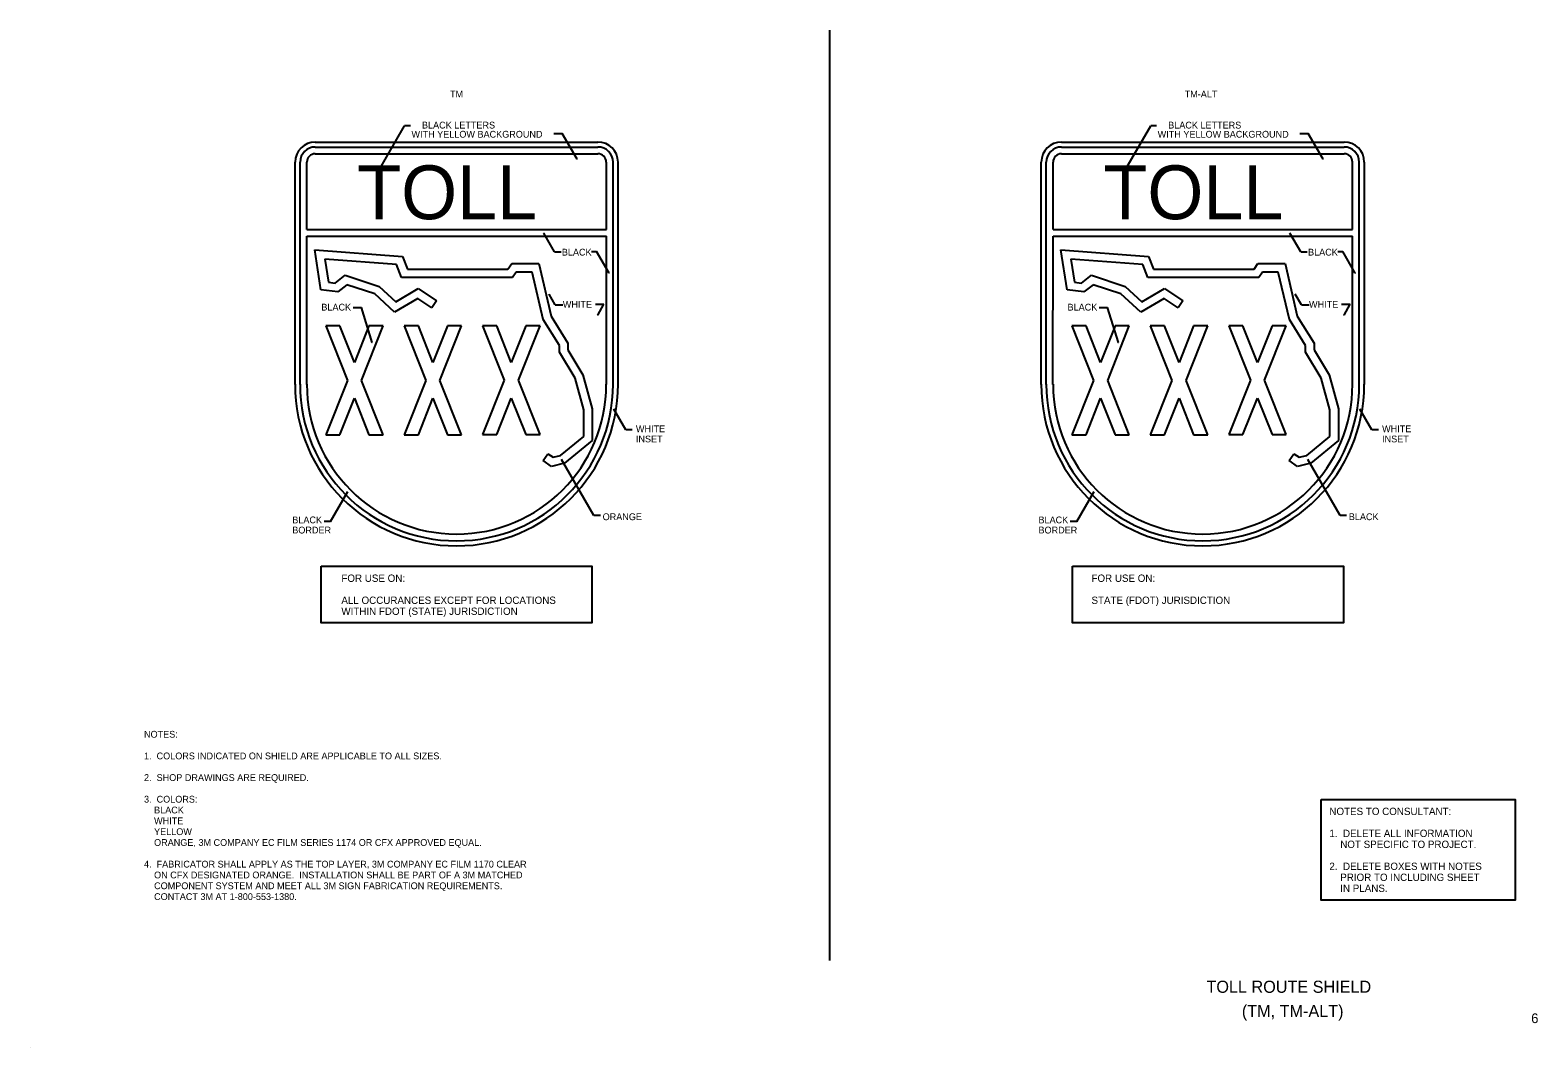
# Model space of a CAD drawing. Extents: x 52204 to 54071, y 10312 to 11572.
import ezdxf

# ---------------------------------------------------------------- set-up
doc = ezdxf.new("R2010")
doc.units = 0
for name, color, linetype in [('AdhocPoint_dp', 7, 'Continuous'), ('Default', 7, 'Continuous'), ('GSDims', 7, 'Continuous'), ('NonPlottingEle_dp', 7, 'Continuous'), ('SignPanel', 7, 'Continuous'), ('TextAlert', 7, 'Continuous'), ('TextMisc', 7, 'Continuous'), ('TextNotes', 7, 'Continuous'), ('TextShtNo', 7, 'Continuous')]:
    doc.layers.add(name, color=color, linetype=linetype)

msp = doc.modelspace()

# ---------------------------------------------------------------- linework, layer by layer
at = {"layer": 'AdhocPoint_dp'}
msp.add_line((52204.2, 10312.4), (52204.2, 10312.4), dxfattribs=at)
at = {"layer": 'GSDims'}
for p, q in [((52634.2, 11395.8), (52667.9, 11454)), ((52675.1, 11454), (52667.9, 11454)), ((52852.7, 11444.4), (52863.1, 11444.4)), ((52881.4, 11412.8), (52863.1, 11444.4)), ((53558.2, 11395.8), (53591.9, 11454)), ((53599.1, 11454), (53591.9, 11454)), ((53776.5, 11444.4), (53786.9, 11444.4)), ((53805.2, 11412.8), (53786.9, 11444.4)), ((52853.5, 11297.9), (52840.1, 11321.1)), ((53777.5, 11297.9), (53764.1, 11321.1)), ((52853.5, 11297.9), (52861.6, 11297.9)), ((52899.3, 11298.3), (52905.5, 11298.3)), ((52921, 11271.5), (52905.5, 11298.3)), ((53777.5, 11297.9), (53785.6, 11297.9)), ((53823.3, 11298.3), (53829.5, 11298.3)), ((53845, 11271.5), (53829.5, 11298.3)), ((52854.4, 11232.5), (52846.8, 11245.6)), ((53778.4, 11232.5), (53770.8, 11245.6)), ((52604, 11228.9), (52614.4, 11228.9)), ((52627.8, 11185.7), (52614.4, 11228.9)), ((52854.4, 11232.5), (52864, 11232.5)), ((52904.2, 11233.3), (52914.7, 11233.3)), ((52907.3, 11219.6), (52914.7, 11233.3)), ((53528, 11228.9), (53538.4, 11228.9)), ((53551.8, 11185.7), (53538.4, 11228.9)), ((53778.4, 11232.5), (53788, 11232.5)), ((53828.2, 11233.3), (53838.7, 11233.3)), ((53831.3, 11219.6), (53838.7, 11233.3)), ((52941.7, 11077.4), (52926.8, 11103.3)), ((53865.7, 11077.4), (53850.8, 11103.3)), ((52949.8, 11077.4), (52941.7, 11077.4)), ((53873.8, 11077.4), (53865.7, 11077.4)), ((52902.4, 10971.4), (52862.3, 11040.9)), ((53826.4, 10971.4), (53786.3, 11040.9)), ((52576.2, 10963.9), (52597.7, 11001.1)), ((53500.2, 10963.9), (53521.8, 11001.1)), ((52576.2, 10963.9), (52568.1, 10963.9)), ((52910.4, 10971.4), (52902.4, 10971.4)), ((53500.2, 10963.9), (53492.2, 10963.9)), ((53834.4, 10971.4), (53826.4, 10971.4))]:
    msp.add_line(p, q, dxfattribs=at)
at = {"layer": 'NonPlottingEle_dp'}
msp.add_line((53194.2, 11572.4), (53194.2, 10420.4), dxfattribs=at)
at = {"layer": 'SignPanel'}
for p, q in [((52557.3, 11433.9), (52907.2, 11433.9)), ((52557.3, 11427.6), (52907.2, 11427.6)), ((53481.3, 11433.9), (53831.2, 11433.9)), ((53481.3, 11427.6), (53831.2, 11427.6)), ((52532.2, 11133.8), (52532.3, 11408.9)), ((52538.4, 11133.8), (52538.5, 11408.9)), ((52546.8, 11325.5), (52546.8, 11408.9)), ((52557.3, 11419.3), (52907.2, 11419.3)), ((52917.8, 11325.5), (52917.8, 11408.9)), ((52926.1, 11133.8), (52926.1, 11408.9)), ((52932.3, 11133.8), (52932.3, 11408.9)), ((53456.2, 11133.8), (53456.3, 11408.9)), ((53462.4, 11133.8), (53462.5, 11408.9)), ((53470.8, 11325.5), (53470.8, 11408.9)), ((53481.3, 11419.3), (53831.2, 11419.3)), ((53841.8, 11325.5), (53841.8, 11408.9)), ((53850.1, 11133.8), (53850.1, 11408.9)), ((53856.3, 11133.8), (53856.3, 11408.9)), ((52546.7, 11133.8), (52546.8, 11317.2)), ((52546.8, 11325.5), (52599, 11325.5)), ((52546.8, 11317.2), (52917.8, 11317.2)), ((52599, 11325.5), (52917.8, 11325.5)), ((52917.8, 11133.8), (52917.8, 11317.2)), ((53470.7, 11133.8), (53470.8, 11317.2)), ((53470.8, 11325.5), (53523, 11325.5)), ((53470.8, 11317.2), (53841.8, 11317.2)), ((53523, 11325.5), (53841.8, 11325.5)), ((53841.8, 11133.8), (53841.8, 11317.2)), ((52556.6, 11300.5), (52665.2, 11292.1)), ((52564.3, 11250.8), (52556.6, 11300.5)), ((53480.6, 11300.5), (53589.2, 11292.1)), ((53488.3, 11250.8), (53480.6, 11300.5)), ((52657.9, 11282.2), (52569, 11289)), ((52569, 11289), (52573.5, 11260.2)), ((52664.1, 11266), (52657.9, 11282.2)), ((52665.2, 11292.1), (52671.3, 11276.5)), ((52671.3, 11276.5), (52795.9, 11276.5)), ((52795.9, 11276.5), (52800.6, 11283.4)), ((52800.6, 11283.4), (52834.2, 11283.4)), ((52834.2, 11283.4), (52849.3, 11218.1)), ((53581.9, 11282.2), (53493, 11289)), ((53493, 11289), (53497.5, 11260.2)), ((53588.2, 11266), (53581.9, 11282.2)), ((53589.2, 11292.1), (53595.3, 11276.5)), ((53595.3, 11276.5), (53719.9, 11276.5)), ((53719.9, 11276.5), (53724.6, 11283.4)), ((53724.6, 11283.4), (53758.2, 11283.4)), ((53758.2, 11283.4), (53773.3, 11218.1)), ((52573.5, 11260.2), (52582.1, 11259.1)), ((52582.1, 11259.1), (52594.4, 11268.9)), ((52594.4, 11268.9), (52636.3, 11255.2)), ((52801.5, 11266), (52664.1, 11266)), ((52806.2, 11272.9), (52801.5, 11266)), ((52825.8, 11272.9), (52806.2, 11272.9)), ((52839.5, 11214), (52825.8, 11272.9)), ((53497.5, 11260.2), (53506.1, 11259.1)), ((53506.1, 11259.1), (53518.4, 11268.9)), ((53518.4, 11268.9), (53560.3, 11255.2)), ((53725.5, 11266), (53588.2, 11266)), ((53730.2, 11272.9), (53725.5, 11266)), ((53749.8, 11272.9), (53730.2, 11272.9)), ((53763.5, 11214), (53749.8, 11272.9)), ((52585.1, 11248.2), (52564.3, 11250.8)), ((52596.5, 11257.2), (52585.1, 11248.2)), ((52630.9, 11246), (52596.5, 11257.2)), ((52655.5, 11223.2), (52630.9, 11246)), ((52636.3, 11255.2), (52656.9, 11236.2)), ((52684.4, 11240.2), (52655.5, 11223.2)), ((52656.9, 11236.2), (52684.8, 11252.6)), ((52701.6, 11228.5), (52684.4, 11240.2)), ((52684.8, 11252.6), (52707.5, 11237.2)), ((53509.1, 11248.2), (53488.3, 11250.8)), ((53520.5, 11257.2), (53509.1, 11248.2)), ((53554.9, 11246), (53520.5, 11257.2)), ((53579.5, 11223.2), (53554.9, 11246)), ((53560.3, 11255.2), (53580.9, 11236.2)), ((53608.4, 11240.2), (53579.5, 11223.2)), ((53580.9, 11236.2), (53608.8, 11252.6)), ((53625.6, 11228.5), (53608.4, 11240.2)), ((53608.8, 11252.6), (53631.5, 11237.2)), ((52707.5, 11237.2), (52701.6, 11228.5)), ((53631.5, 11237.2), (53625.6, 11228.5)), ((52587.8, 11206.1), (52570.2, 11206.1)), ((52570.2, 11206.1), (52597, 11138.7)), ((52605.7, 11160.8), (52587.8, 11206.1)), ((52623.7, 11206.1), (52605.7, 11160.8)), ((52614.5, 11138.7), (52641.3, 11206.1)), ((52641.3, 11206.1), (52623.7, 11206.1)), ((52684.9, 11206.2), (52667.3, 11206.2)), ((52667.3, 11206.2), (52694.1, 11138.8)), ((52702.9, 11160.9), (52684.9, 11206.2)), ((52720.9, 11206.2), (52702.9, 11160.9)), ((52711.7, 11138.8), (52738.4, 11206.2)), ((52738.4, 11206.2), (52720.9, 11206.2)), ((52782, 11206.3), (52764.5, 11206.3)), ((52764.5, 11206.3), (52791.2, 11138.9)), ((52800, 11161), (52782, 11206.3)), ((52818, 11206.3), (52800, 11161)), ((52808.8, 11138.9), (52835.6, 11206.3)), ((52835.6, 11206.3), (52818, 11206.3)), ((52859.5, 11181.9), (52839.5, 11214)), ((52849.3, 11218.1), (52870, 11184.9)), ((53511.8, 11206.1), (53494.2, 11206.1)), ((53494.2, 11206.1), (53521, 11138.7)), ((53529.7, 11160.8), (53511.8, 11206.1)), ((53547.7, 11206.1), (53529.7, 11160.8)), ((53538.5, 11138.7), (53565.3, 11206.1)), ((53565.3, 11206.1), (53547.7, 11206.1)), ((53608.9, 11206.2), (53591.3, 11206.2)), ((53591.3, 11206.2), (53618.1, 11138.8)), ((53626.9, 11160.9), (53608.9, 11206.2)), ((53644.9, 11206.2), (53626.9, 11160.9)), ((53635.7, 11138.8), (53662.4, 11206.2)), ((53662.4, 11206.2), (53644.9, 11206.2)), ((53706, 11206.3), (53688.5, 11206.3)), ((53688.5, 11206.3), (53715.2, 11138.9)), ((53724, 11161), (53706, 11206.3)), ((53742, 11206.3), (53724, 11161)), ((53732.8, 11138.9), (53759.6, 11206.3)), ((53759.6, 11206.3), (53742, 11206.3)), ((53783.5, 11181.9), (53763.5, 11214)), ((53773.3, 11218.1), (53794, 11184.9)), ((52870, 11184.9), (52870, 11176.5)), ((53794, 11184.9), (53794, 11176.5)), ((52859.5, 11173.6), (52859.5, 11181.9)), ((52879, 11141.5), (52859.5, 11173.6)), ((52870, 11176.5), (52888.7, 11145.7)), ((53783.5, 11173.6), (53783.5, 11181.9)), ((53803, 11141.5), (53783.5, 11173.6)), ((53794, 11176.5), (53812.7, 11145.7)), ((52888.7, 11145.7), (52900.2, 11103.6)), ((53812.7, 11145.7), (53824.2, 11103.6)), ((52597, 11138.7), (52570.2, 11071.4)), ((52641.3, 11071.4), (52614.5, 11138.7)), ((52694.1, 11138.8), (52667.3, 11071.5)), ((52738.4, 11071.5), (52711.7, 11138.8)), ((52791.2, 11138.9), (52764.5, 11071.6)), ((52835.6, 11071.6), (52808.8, 11138.9)), ((52889.7, 11102.2), (52879, 11141.5)), ((53521, 11138.7), (53494.2, 11071.4)), ((53565.3, 11071.4), (53538.5, 11138.7)), ((53618.1, 11138.8), (53591.3, 11071.5)), ((53662.4, 11071.5), (53635.7, 11138.8)), ((53715.2, 11138.9), (53688.5, 11071.6)), ((53759.6, 11071.6), (53732.8, 11138.9)), ((53813.7, 11102.2), (53803, 11141.5)), ((52587.8, 11071.4), (52605.7, 11116.6)), ((52605.7, 11116.6), (52623.7, 11071.4)), ((52684.9, 11071.5), (52702.9, 11116.7)), ((52702.9, 11116.7), (52720.9, 11071.5)), ((52782, 11071.6), (52800, 11116.9)), ((52800, 11116.9), (52818, 11071.6)), ((53511.8, 11071.4), (53529.8, 11116.6)), ((53529.8, 11116.6), (53547.7, 11071.4)), ((53608.9, 11071.5), (53626.9, 11116.7)), ((53626.9, 11116.7), (53644.9, 11071.5)), ((53706, 11071.6), (53724, 11116.9)), ((53724, 11116.9), (53742, 11071.6)), ((52889.7, 11069.2), (52889.7, 11102.2)), ((52900.2, 11103.6), (52900.2, 11064.3)), ((53813.7, 11069.2), (53813.7, 11102.2)), ((53824.2, 11103.6), (53824.2, 11064.3)), ((52570.2, 11071.4), (52587.8, 11071.4)), ((52623.7, 11071.4), (52641.3, 11071.4)), ((52667.3, 11071.5), (52684.9, 11071.5)), ((52720.9, 11071.5), (52738.4, 11071.5)), ((52764.5, 11071.6), (52782, 11071.6)), ((52818, 11071.6), (52835.6, 11071.6)), ((53494.2, 11071.4), (53511.8, 11071.4)), ((53547.7, 11071.4), (53565.3, 11071.4)), ((53591.3, 11071.5), (53608.9, 11071.5)), ((53644.9, 11071.5), (53662.4, 11071.5)), ((53688.5, 11071.6), (53706, 11071.6)), ((53742, 11071.6), (53759.6, 11071.6)), ((52861.1, 11045.8), (52889.7, 11069.2)), ((52900.2, 11064.3), (52865.9, 11036.1)), ((53785.1, 11045.8), (53813.7, 11069.2)), ((53824.2, 11064.3), (53789.9, 11036.1)), ((52839.3, 11039.4), (52845.2, 11048)), ((52849.6, 11032.2), (52839.3, 11039.4)), ((52845.2, 11048), (52851.7, 11043.5)), ((52865.9, 11036.1), (52849.6, 11032.2)), ((52851.7, 11043.5), (52861.1, 11045.8)), ((53763.3, 11039.4), (53769.2, 11048)), ((53773.6, 11032.2), (53763.3, 11039.4)), ((53769.2, 11048), (53775.7, 11043.5)), ((53789.9, 11036.1), (53773.6, 11032.2)), ((53775.7, 11043.5), (53785.1, 11045.8))]:
    msp.add_line(p, q, dxfattribs=at)
for centre, radius, start, end in [((52557.3, 11408.9), 25, 90, 179.9792), ((52557.3, 11408.9), 18.8, 90, 179.9792), ((52907.2, 11408.9), 25, 0, 90), ((52907.2, 11408.9), 18.8, 0, 90), ((53481.3, 11408.9), 25, 90, 179.9792), ((53481.3, 11408.9), 18.8, 90, 179.9792), ((53831.2, 11408.9), 25, 0, 90), ((53831.2, 11408.9), 18.8, 0, 90), ((52557.3, 11408.9), 10.4, 90, 179.9792), ((52907.2, 11408.9), 10.4, 0, 90), ((53481.3, 11408.9), 10.4, 90, 179.9792), ((53831.2, 11408.9), 10.4, 0, 90), ((52732.2, 11133.9), 200, 180, 0), ((52732.2, 11133.9), 193.8, 180, 0), ((52732.2, 11133.9), 185.4, 180, 0), ((53656.2, 11133.9), 200, 180, 0), ((53656.2, 11133.9), 193.8, 180, 0), ((53656.2, 11133.9), 185.4, 180, 0)]:
    msp.add_arc(centre, radius, start, end, dxfattribs=at)
at = {"layer": 'TextAlert'}
for points in [[(52564.4, 10908.9), (52899.9, 10908.9), (52899.9, 10838.4), (52564.4, 10838.4)], [(53495, 10908.9), (53830.5, 10908.9), (53830.5, 10838.4), (53495, 10838.4)], [(53803, 10619.7), (54043.2, 10619.7), (54043.2, 10495.4), (53803, 10495.4)]]:
    msp.add_lwpolyline(points, close=True, dxfattribs=at)

# ---------------------------------------------------------------- texts
at = {"layer": 'Default'}
for s, p in [('TM', (52724.1, 11489)), ('TM-ALT', (53633.8, 11489))]:
    msp.add_text(s, height=8.4, dxfattribs=at).set_placement(p)
at = {"layer": 'GSDims'}
for s, p in [('WITH YELLOW BACKGROUND', (52676.4, 11439.3)), ('BLACK LETTERS', (52689.4, 11450.6)), ('WITH YELLOW BACKGROUND', (53600.4, 11439.3)), ('BLACK LETTERS', (53613.4, 11450.6)), ('.', (52632.7, 11395.1)), ('.', (53556.7, 11395.1)), ('BLACK', (52862.6, 11293.3)), ('BLACK', (53786.6, 11293.3)), ('.', (52845, 11244.5)), ('.', (53769, 11244.5)), ('BLACK', (52564.8, 11225.2)), ('WHITE', (52863.8, 11228.7)), ('BLACK', (53488.8, 11225.2)), ('WHITE', (53787.8, 11228.7)), ('.', (52626, 11184.6)), ('.', (53550, 11184.6)), ('.', (52925, 11102.1)), ('.', (53849, 11102.1)), ('WHITE', (52954.3, 11074.6)), ('WHITE', (53878.3, 11074.6)), ('INSET', (52954.3, 11062)), ('INSET', (53878.3, 11062)), ('.', (52860.5, 11039.6)), ('.', (53784.5, 11039.6)), ('.', (52595.9, 10999.8)), ('.', (53519.9, 10999.8)), ('BLACK', (52528.8, 10961.8)), ('ORANGE', (52913.1, 10965.7)), ('BLACK', (53452.8, 10961.8)), ('BLACK', (53837.1, 10965.7)), ('BORDER', (52528.8, 10949.2)), ('BORDER', (53452.8, 10949.2))]:
    msp.add_text(s, height=8.4, dxfattribs=at).set_placement(p)
for rotation, p in [(90, (52882.2, 11410.8)), (90, (53806.1, 11410.8)), (90, (52841.1, 11319.5)), (90, (53765.1, 11319.5)), (301.5608, (52905.4, 11220.5)), (301.5608, (53829.4, 11220.5))]:
    msp.add_text('.', height=8.4, rotation=rotation, dxfattribs=at).set_placement(p)
at = {"layer": 'SignPanel'}
for p in [(52609.2, 11338.3), (53533.2, 11338.3)]:
    msp.add_text('TOLL', height=66.65, dxfattribs=at).set_placement(p)
for p in [(52922, 11270), (53846, 11270)]:
    msp.add_text('.', height=7.2, rotation=90, dxfattribs=at).set_placement(p)
at = {"layer": 'TextAlert'}
for s, p in [('FOR USE ON:', (52589.6, 10889.3)), ('FOR USE ON:', (53518.4, 10889.3)), ('ALL OCCURANCES EXCEPT FOR LOCATIONS', (52589.6, 10862)), ('STATE (FDOT) JURISDICTION', (53518.4, 10862)), ('WITHIN FDOT (STATE) JURISDICTION', (52589.6, 10848.4)), ('NOTES TO CONSULTANT:', (53813, 10600.6)), ('1.  DELETE ALL INFORMATION', (53813, 10573.4)), ('    NOT SPECIFIC TO PROJECT.', (53813, 10559.8)), ('2.  DELETE BOXES WITH NOTES', (53813, 10532.6)), ('    PRIOR TO INCLUDING SHEET', (53813, 10519)), ('    IN PLANS.', (53813, 10505.4))]:
    msp.add_text(s, height=9.072, dxfattribs=at).set_placement(p)
at = {"layer": 'TextMisc'}
for s, p in [('   TOLL ROUTE SHIELD    ', (53644.1, 10380.5)), ('      (TM, TM-ALT)      ', (53671.2, 10350.5))]:
    msp.add_text(s, height=15, rotation=360, dxfattribs=at).set_placement(p)
at = {"layer": 'TextNotes'}
for s, p in [('NOTES:', (52345.2, 10696.4)), ('1.  COLORS INDICATED ON SHIELD ARE APPLICABLE TO ALL SIZES.', (52345.2, 10669.6)), ('2.  SHOP DRAWINGS ARE REQUIRED.', (52345.2, 10642.8)), ('3.  COLORS:', (52345.2, 10616)), ('    BLACK', (52345.2, 10602.6)), ('    WHITE', (52345.2, 10589.2)), ('    YELLOW', (52345.2, 10575.8)), ('    ORANGE, 3M COMPANY EC FILM SERIES 1174 OR CFX APPROVED EQUAL.', (52345.2, 10562.4)), ('4.  FABRICATOR SHALL APPLY AS THE TOP LAYER, 3M COMPANY EC FILM 1170 CLEAR', (52345.2, 10535.6)), ('    ON CFX DESIGNATED ORANGE.  INSTALLATION SHALL BE PART OF A 3M MATCHED', (52345.2, 10522.2)), ('    COMPONENT SYSTEM AND MEET ALL 3M SIGN FABRICATION REQUIREMENTS.', (52345.2, 10508.8)), ('    CONTACT 3M AT 1-800-553-1380.', (52345.2, 10495.4))]:
    msp.add_text(s, height=8.4, dxfattribs=at).set_placement(p)
at = {"layer": 'TextShtNo'}
msp.add_text('  6  ', height=12, rotation=360, dxfattribs=at).set_placement((54054, 10343))

doc.saveas('drawing.dxf')
